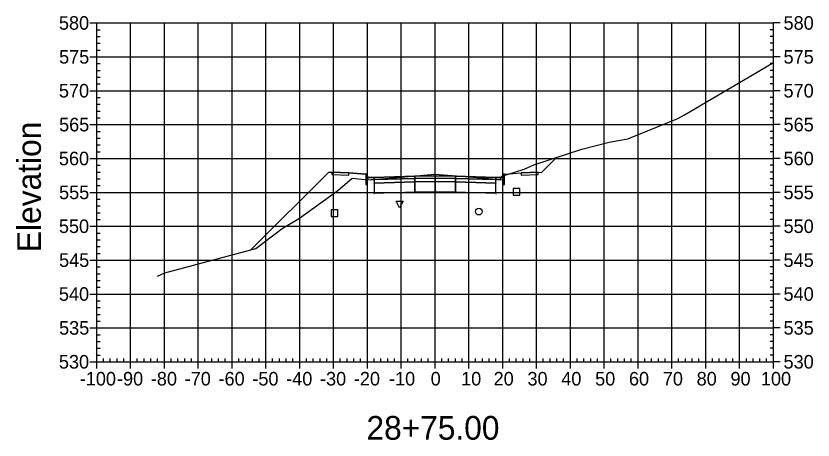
# Model space of a CAD drawing. Extents: x 704834 to 709892, y 372981 to 377533.
# Drawn here: x 708281 to 708516.6, y 377097.7 to 377222.9 of the extents above; entities that cross this region are included whole.
import ezdxf

# ---------------------------------------------------------------- set-up
doc = ezdxf.new("R2010")
doc.units = 0
for name, color, linetype in [('1', 7, 'Continuous'), ('10', 7, 'Continuous'), ('13', 7, 'Continuous'), ('14', 7, 'Continuous'), ('4', 7, 'Continuous'), ('57', 7, 'Continuous'), ('60', 7, 'Continuous'), ('Default_Xsect', 7, 'Continuous'), ('Existing', 7, 'Continuous')]:
    doc.layers.add(name, color=color, linetype=linetype)

msp = doc.modelspace()

# ---------------------------------------------------------------- linework, layer by layer
for points in [[(708436.41, 377176.72), (708440.81, 377181.12)], [(708373.41, 377176.72), (708350.61, 377153.92)], [(708374.41, 377176.76), (708373.41, 377176.72)], [(708435.41, 377176.76), (708436.41, 377176.72)], [(708384.41, 377176.16), (708379.41, 377176.56)], [(708425.41, 377176.16), (708430.41, 377176.56)]]:
    msp.add_lwpolyline(points)
for points in [[(708379.41, 377176.56), (708374.41, 377176.76), (708374.41, 377176.09), (708379.41, 377175.89)], [(708430.41, 377175.89), (708435.41, 377176.09), (708435.41, 377176.76), (708430.41, 377176.56)], [(708384.91, 377175.16), (708384.83, 377176.16), (708384.41, 377176.16), (708384.41, 377173.16), (708384.91, 377173.16)], [(708386.91, 377175.24), (708384.91, 377175.16), (708384.91, 377174.49), (708386.91, 377174.57)], [(708398.91, 377175.6), (708386.91, 377175.24), (708386.91, 377174.57), (708398.91, 377174.93)], [(708398.91, 377174.93), (708386.91, 377174.57), (708386.91, 377173.57), (708398.91, 377173.93)], [(708398.86, 377174.88), (708398.96, 377174.88), (708398.96, 377174.98), (708398.86, 377174.98)], [(708404.91, 377175.72), (708398.91, 377175.6), (708398.91, 377174.93), (708404.91, 377175.05)], [(708404.91, 377175.05), (708398.91, 377174.93), (708398.91, 377173.93), (708404.91, 377174.05)], [(708404.86, 377175), (708404.96, 377175), (708404.96, 377175.1), (708404.86, 377175.1)], [(708404.91, 377175.05), (708410.91, 377174.93), (708410.91, 377175.6), (708404.91, 377175.72)], [(708404.91, 377174.05), (708410.91, 377173.93), (708410.91, 377174.93), (708404.91, 377175.05)], [(708410.86, 377174.88), (708410.96, 377174.88), (708410.96, 377174.98), (708410.86, 377174.98)], [(708410.91, 377174.93), (708422.91, 377174.57), (708422.91, 377175.24), (708410.91, 377175.6)], [(708410.91, 377173.93), (708422.91, 377173.57), (708422.91, 377174.57), (708410.91, 377174.93)], [(708422.91, 377174.57), (708424.91, 377174.49), (708424.91, 377175.16), (708422.91, 377175.24)], [(708424.91, 377173.16), (708425.41, 377173.16), (708425.41, 377176.16), (708425, 377176.16), (708424.91, 377175.16)], [(708386.86, 377173.52), (708386.96, 377173.52), (708386.96, 377173.62), (708386.86, 377173.62)], [(708398.91, 377173.93), (708386.91, 377173.57), (708386.91, 377170.57), (708398.91, 377170.93)], [(708398.86, 377173.88), (708398.96, 377173.88), (708398.96, 377173.98), (708398.86, 377173.98)], [(708404.91, 377174.05), (708398.91, 377173.93), (708398.91, 377170.93), (708404.91, 377171.05)], [(708404.86, 377174), (708404.96, 377174), (708404.96, 377174.1), (708404.86, 377174.1)], [(708404.91, 377171.05), (708410.91, 377170.93), (708410.91, 377173.93), (708404.91, 377174.05)], [(708410.86, 377173.88), (708410.96, 377173.88), (708410.96, 377173.98), (708410.86, 377173.98)], [(708410.91, 377170.93), (708422.91, 377170.57), (708422.91, 377173.57), (708410.91, 377173.93)], [(708422.86, 377173.52), (708422.96, 377173.52), (708422.96, 377173.62), (708422.86, 377173.62)], [(708386.86, 377170.52), (708386.96, 377170.52), (708386.96, 377170.62), (708386.86, 377170.62)], [(708398.86, 377170.88), (708398.96, 377170.88), (708398.96, 377170.98), (708398.86, 377170.98)], [(708404.86, 377171), (708404.96, 377171), (708404.96, 377171.1), (708404.86, 377171.1)], [(708410.86, 377170.88), (708410.96, 377170.88), (708410.96, 377170.98), (708410.86, 377170.98)], [(708422.86, 377170.52), (708422.96, 377170.52), (708422.96, 377170.62), (708422.86, 377170.62)]]:
    msp.add_lwpolyline(points, close=True)
at = {"layer": '1'}
msp.add_lwpolyline([(708394.45, 377166.26), (708393.45, 377168.26), (708395.45, 377168.26)], close=True, dxfattribs=at)
at = {"layer": '10'}
msp.add_lwpolyline([(708374.17, 377163.68), (708376.17, 377163.68), (708376.17, 377165.68), (708374.17, 377165.68)], close=True, dxfattribs=at)
at = {"layer": '13'}
msp.add_circle((708417.85, 377165.14), 1, dxfattribs=at)
at = {"layer": '14'}
for points in [[(708440.81, 377181.12), (708440.81, 377181.17), (708440.81, 377181.12), (708440.76, 377181.12), (708440.81, 377181.12), (708440.81, 377181.07), (708440.81, 377181.12), (708440.86, 377181.12)], [(708386.91, 377175.24), (708386.91, 377175.29), (708386.91, 377175.24), (708386.86, 377175.24), (708386.91, 377175.24), (708386.91, 377175.19), (708386.91, 377175.24), (708386.96, 377175.24)], [(708404.91, 377175.72), (708404.91, 377175.77), (708404.91, 377175.72), (708404.86, 377175.72), (708404.91, 377175.72), (708404.91, 377175.67), (708404.91, 377175.72), (708404.96, 377175.72)], [(708422.91, 377175.24), (708422.91, 377175.29), (708422.91, 377175.24), (708422.86, 377175.24), (708422.91, 377175.24), (708422.91, 377175.19), (708422.91, 377175.24), (708422.96, 377175.24)], [(708350.61, 377153.92), (708350.61, 377153.97), (708350.61, 377153.92), (708350.56, 377153.92), (708350.61, 377153.92), (708350.61, 377153.87), (708350.61, 377153.92), (708350.66, 377153.92)]]:
    msp.add_lwpolyline(points, dxfattribs=at)
at = {"layer": '4'}
msp.add_lwpolyline([(708427.97, 377169.95), (708429.97, 377169.95), (708429.97, 377171.95), (708427.97, 377171.95)], close=True, dxfattribs=at)
at = {"layer": '57'}
for p, q in [((708302.91, 377220.82), (708304.91, 377220.82)), ((708304.91, 377220.82), (708504.91, 377220.82)), ((708304.91, 377120.82), (708304.91, 377220.82)), ((708304.91, 377120.82), (708304.91, 377220.82)), ((708314.91, 377120.82), (708314.91, 377220.82)), ((708324.91, 377120.82), (708324.91, 377220.82)), ((708334.91, 377120.82), (708334.91, 377220.82)), ((708344.91, 377120.82), (708344.91, 377220.82)), ((708354.91, 377120.82), (708354.91, 377220.82)), ((708364.91, 377120.82), (708364.91, 377220.82)), ((708374.91, 377120.82), (708374.91, 377220.82)), ((708384.91, 377120.82), (708384.91, 377220.82)), ((708394.91, 377120.82), (708394.91, 377220.82)), ((708404.91, 377120.82), (708404.91, 377220.82)), ((708414.91, 377120.82), (708414.91, 377220.82)), ((708424.91, 377120.82), (708424.91, 377220.82)), ((708434.91, 377120.82), (708434.91, 377220.82)), ((708444.91, 377120.82), (708444.91, 377220.82)), ((708454.91, 377120.82), (708454.91, 377220.82)), ((708464.91, 377120.82), (708464.91, 377220.82)), ((708474.91, 377120.82), (708474.91, 377220.82)), ((708484.91, 377120.82), (708484.91, 377220.82)), ((708494.91, 377120.82), (708494.91, 377220.82)), ((708504.91, 377120.82), (708504.91, 377220.82)), ((708504.91, 377120.82), (708504.91, 377220.82)), ((708506.91, 377220.82), (708504.91, 377220.82)), ((708304.91, 377218.82), (708305.91, 377218.82)), ((708304.91, 377216.82), (708305.91, 377216.82)), ((708504.91, 377218.82), (708503.91, 377218.82)), ((708504.91, 377216.82), (708503.91, 377216.82)), ((708304.91, 377214.82), (708305.91, 377214.82)), ((708504.91, 377214.82), (708503.91, 377214.82)), ((708304.91, 377212.82), (708305.91, 377212.82)), ((708504.91, 377212.82), (708503.91, 377212.82)), ((708302.91, 377210.82), (708304.91, 377210.82)), ((708304.91, 377210.82), (708504.91, 377210.82)), ((708506.91, 377210.82), (708504.91, 377210.82)), ((708304.91, 377208.82), (708305.91, 377208.82)), ((708504.91, 377208.82), (708503.91, 377208.82)), ((708304.91, 377206.82), (708305.91, 377206.82)), ((708504.91, 377206.82), (708503.91, 377206.82)), ((708304.91, 377204.82), (708305.91, 377204.82)), ((708304.91, 377202.82), (708305.91, 377202.82)), ((708504.91, 377204.82), (708503.91, 377204.82)), ((708504.91, 377202.82), (708503.91, 377202.82)), ((708302.91, 377200.82), (708304.91, 377200.82)), ((708304.91, 377200.82), (708504.91, 377200.82)), ((708506.91, 377200.82), (708504.91, 377200.82)), ((708304.91, 377198.82), (708305.91, 377198.82)), ((708504.91, 377198.82), (708503.91, 377198.82)), ((708304.91, 377196.82), (708305.91, 377196.82)), ((708504.91, 377196.82), (708503.91, 377196.82)), ((708304.91, 377194.82), (708305.91, 377194.82)), ((708504.91, 377194.82), (708503.91, 377194.82)), ((708302.91, 377190.82), (708304.91, 377190.82)), ((708304.91, 377192.82), (708305.91, 377192.82)), ((708304.91, 377190.82), (708504.91, 377190.82)), ((708504.91, 377192.82), (708503.91, 377192.82)), ((708506.91, 377190.82), (708504.91, 377190.82)), ((708304.91, 377188.82), (708305.91, 377188.82)), ((708504.91, 377188.82), (708503.91, 377188.82)), ((708304.91, 377186.82), (708305.91, 377186.82)), ((708504.91, 377186.82), (708503.91, 377186.82)), ((708304.91, 377184.82), (708305.91, 377184.82)), ((708504.91, 377184.82), (708503.91, 377184.82)), ((708304.91, 377182.82), (708305.91, 377182.82)), ((708504.91, 377182.82), (708503.91, 377182.82)), ((708302.91, 377180.82), (708304.91, 377180.82)), ((708304.91, 377180.82), (708504.91, 377180.82)), ((708506.91, 377180.82), (708504.91, 377180.82)), ((708304.91, 377178.82), (708305.91, 377178.82)), ((708304.91, 377176.82), (708305.91, 377176.82)), ((708504.91, 377178.82), (708503.91, 377178.82)), ((708504.91, 377176.82), (708503.91, 377176.82)), ((708304.91, 377174.82), (708305.91, 377174.82)), ((708504.91, 377174.82), (708503.91, 377174.82)), ((708304.91, 377172.82), (708305.91, 377172.82)), ((708504.91, 377172.82), (708503.91, 377172.82)), ((708302.91, 377170.82), (708304.91, 377170.82)), ((708304.91, 377170.82), (708504.91, 377170.82)), ((708506.91, 377170.82), (708504.91, 377170.82)), ((708304.91, 377168.82), (708305.91, 377168.82)), ((708504.91, 377168.82), (708503.91, 377168.82)), ((708304.91, 377166.82), (708305.91, 377166.82)), ((708304.91, 377164.82), (708305.91, 377164.82)), ((708504.91, 377166.82), (708503.91, 377166.82)), ((708504.91, 377164.82), (708503.91, 377164.82)), ((708304.91, 377162.82), (708305.91, 377162.82)), ((708504.91, 377162.82), (708503.91, 377162.82)), ((708302.91, 377160.82), (708304.91, 377160.82)), ((708304.91, 377160.82), (708504.91, 377160.82)), ((708506.91, 377160.82), (708504.91, 377160.82)), ((708304.91, 377158.82), (708305.91, 377158.82)), ((708504.91, 377158.82), (708503.91, 377158.82)), ((708304.91, 377156.82), (708305.91, 377156.82)), ((708504.91, 377156.82), (708503.91, 377156.82)), ((708304.91, 377154.82), (708305.91, 377154.82)), ((708504.91, 377154.82), (708503.91, 377154.82)), ((708302.91, 377150.82), (708304.91, 377150.82)), ((708304.91, 377152.82), (708305.91, 377152.82)), ((708304.91, 377150.82), (708504.91, 377150.82)), ((708504.91, 377152.82), (708503.91, 377152.82)), ((708506.91, 377150.82), (708504.91, 377150.82)), ((708304.91, 377148.82), (708305.91, 377148.82)), ((708504.91, 377148.82), (708503.91, 377148.82)), ((708304.91, 377146.82), (708305.91, 377146.82)), ((708504.91, 377146.82), (708503.91, 377146.82)), ((708304.91, 377144.82), (708305.91, 377144.82)), ((708504.91, 377144.82), (708503.91, 377144.82)), ((708304.91, 377142.82), (708305.91, 377142.82)), ((708504.91, 377142.82), (708503.91, 377142.82)), ((708302.91, 377140.82), (708304.91, 377140.82)), ((708304.91, 377140.82), (708504.91, 377140.82)), ((708506.91, 377140.82), (708504.91, 377140.82)), ((708304.91, 377138.82), (708305.91, 377138.82)), ((708304.91, 377136.82), (708305.91, 377136.82)), ((708504.91, 377138.82), (708503.91, 377138.82)), ((708504.91, 377136.82), (708503.91, 377136.82)), ((708304.91, 377134.82), (708305.91, 377134.82)), ((708504.91, 377134.82), (708503.91, 377134.82)), ((708304.91, 377132.82), (708305.91, 377132.82)), ((708504.91, 377132.82), (708503.91, 377132.82)), ((708302.91, 377130.82), (708304.91, 377130.82)), ((708304.91, 377130.82), (708504.91, 377130.82)), ((708506.91, 377130.82), (708504.91, 377130.82)), ((708304.91, 377128.82), (708305.91, 377128.82)), ((708504.91, 377128.82), (708503.91, 377128.82)), ((708304.91, 377126.82), (708305.91, 377126.82)), ((708304.91, 377124.82), (708305.91, 377124.82)), ((708504.91, 377126.82), (708503.91, 377126.82)), ((708504.91, 377124.82), (708503.91, 377124.82)), ((708304.91, 377122.82), (708305.91, 377122.82)), ((708504.91, 377122.82), (708503.91, 377122.82)), ((708302.91, 377120.82), (708304.91, 377120.82)), ((708304.91, 377120.82), (708504.91, 377120.82)), ((708304.91, 377120.82), (708504.91, 377120.82)), ((708304.91, 377118.82), (708304.91, 377120.82)), ((708306.91, 377120.82), (708306.91, 377121.82)), ((708308.91, 377120.82), (708308.91, 377121.82)), ((708310.91, 377120.82), (708310.91, 377121.82)), ((708312.91, 377120.82), (708312.91, 377121.82)), ((708314.91, 377118.82), (708314.91, 377120.82)), ((708316.91, 377120.82), (708316.91, 377121.82)), ((708318.91, 377120.82), (708318.91, 377121.82)), ((708320.91, 377120.82), (708320.91, 377121.82)), ((708322.91, 377120.82), (708322.91, 377121.82)), ((708324.91, 377118.82), (708324.91, 377120.82)), ((708326.91, 377120.82), (708326.91, 377121.82)), ((708328.91, 377120.82), (708328.91, 377121.82)), ((708330.91, 377120.82), (708330.91, 377121.82)), ((708332.91, 377120.82), (708332.91, 377121.82)), ((708334.91, 377118.82), (708334.91, 377120.82)), ((708336.91, 377120.82), (708336.91, 377121.82)), ((708338.91, 377120.82), (708338.91, 377121.82)), ((708340.91, 377120.82), (708340.91, 377121.82)), ((708342.91, 377120.82), (708342.91, 377121.82)), ((708344.91, 377118.82), (708344.91, 377120.82)), ((708346.91, 377120.82), (708346.91, 377121.82)), ((708348.91, 377120.82), (708348.91, 377121.82)), ((708350.91, 377120.82), (708350.91, 377121.82)), ((708352.91, 377120.82), (708352.91, 377121.82)), ((708354.91, 377118.82), (708354.91, 377120.82)), ((708356.91, 377120.82), (708356.91, 377121.82)), ((708358.91, 377120.82), (708358.91, 377121.82)), ((708360.91, 377120.82), (708360.91, 377121.82)), ((708362.91, 377120.82), (708362.91, 377121.82)), ((708364.91, 377118.82), (708364.91, 377120.82)), ((708366.91, 377120.82), (708366.91, 377121.82)), ((708368.91, 377120.82), (708368.91, 377121.82)), ((708370.91, 377120.82), (708370.91, 377121.82)), ((708372.91, 377120.82), (708372.91, 377121.82)), ((708374.91, 377118.82), (708374.91, 377120.82)), ((708376.91, 377120.82), (708376.91, 377121.82)), ((708378.91, 377120.82), (708378.91, 377121.82)), ((708380.91, 377120.82), (708380.91, 377121.82)), ((708382.91, 377120.82), (708382.91, 377121.82)), ((708384.91, 377118.82), (708384.91, 377120.82)), ((708386.91, 377120.82), (708386.91, 377121.82)), ((708388.91, 377120.82), (708388.91, 377121.82)), ((708390.91, 377120.82), (708390.91, 377121.82)), ((708392.91, 377120.82), (708392.91, 377121.82)), ((708394.91, 377118.82), (708394.91, 377120.82)), ((708396.91, 377120.82), (708396.91, 377121.82)), ((708398.91, 377120.82), (708398.91, 377121.82)), ((708400.91, 377120.82), (708400.91, 377121.82)), ((708402.91, 377120.82), (708402.91, 377121.82)), ((708404.91, 377118.82), (708404.91, 377120.82)), ((708406.91, 377120.82), (708406.91, 377121.82)), ((708408.91, 377120.82), (708408.91, 377121.82)), ((708410.91, 377120.82), (708410.91, 377121.82)), ((708412.91, 377120.82), (708412.91, 377121.82)), ((708414.91, 377118.82), (708414.91, 377120.82)), ((708416.91, 377120.82), (708416.91, 377121.82)), ((708418.91, 377120.82), (708418.91, 377121.82)), ((708420.91, 377120.82), (708420.91, 377121.82)), ((708422.91, 377120.82), (708422.91, 377121.82)), ((708424.91, 377118.82), (708424.91, 377120.82)), ((708426.91, 377120.82), (708426.91, 377121.82)), ((708428.91, 377120.82), (708428.91, 377121.82)), ((708430.91, 377120.82), (708430.91, 377121.82)), ((708432.91, 377120.82), (708432.91, 377121.82)), ((708434.91, 377118.82), (708434.91, 377120.82)), ((708436.91, 377120.82), (708436.91, 377121.82)), ((708438.91, 377120.82), (708438.91, 377121.82)), ((708440.91, 377120.82), (708440.91, 377121.82)), ((708442.91, 377120.82), (708442.91, 377121.82)), ((708444.91, 377118.82), (708444.91, 377120.82)), ((708446.91, 377120.82), (708446.91, 377121.82)), ((708448.91, 377120.82), (708448.91, 377121.82)), ((708450.91, 377120.82), (708450.91, 377121.82)), ((708452.91, 377120.82), (708452.91, 377121.82)), ((708454.91, 377118.82), (708454.91, 377120.82)), ((708456.91, 377120.82), (708456.91, 377121.82)), ((708458.91, 377120.82), (708458.91, 377121.82)), ((708460.91, 377120.82), (708460.91, 377121.82)), ((708462.91, 377120.82), (708462.91, 377121.82)), ((708464.91, 377118.82), (708464.91, 377120.82)), ((708466.91, 377120.82), (708466.91, 377121.82)), ((708468.91, 377120.82), (708468.91, 377121.82)), ((708470.91, 377120.82), (708470.91, 377121.82)), ((708472.91, 377120.82), (708472.91, 377121.82)), ((708474.91, 377118.82), (708474.91, 377120.82)), ((708476.91, 377120.82), (708476.91, 377121.82)), ((708478.91, 377120.82), (708478.91, 377121.82)), ((708480.91, 377120.82), (708480.91, 377121.82)), ((708482.91, 377120.82), (708482.91, 377121.82)), ((708484.91, 377118.82), (708484.91, 377120.82)), ((708486.91, 377120.82), (708486.91, 377121.82)), ((708488.91, 377120.82), (708488.91, 377121.82)), ((708490.91, 377120.82), (708490.91, 377121.82)), ((708492.91, 377120.82), (708492.91, 377121.82)), ((708494.91, 377118.82), (708494.91, 377120.82)), ((708496.91, 377120.82), (708496.91, 377121.82)), ((708498.91, 377120.82), (708498.91, 377121.82)), ((708500.91, 377120.82), (708500.91, 377121.82)), ((708502.91, 377120.82), (708502.91, 377121.82)), ((708504.91, 377118.82), (708504.91, 377120.82)), ((708506.91, 377120.82), (708504.91, 377120.82))]:
    msp.add_line(p, q, dxfattribs=at)
at = {"layer": 'Default_Xsect'}
msp.add_lwpolyline([(708350.61, 377153.92), (708373.41, 377176.72), (708374.41, 377176.76), (708379.41, 377176.56), (708384.41, 377176.16), (708384.83, 377176.16), (708384.91, 377175.16), (708386.91, 377175.24), (708398.91, 377175.6), (708404.91, 377175.72), (708410.91, 377175.6), (708422.91, 377175.24), (708424.91, 377175.16), (708425, 377176.16), (708425.41, 377176.16), (708430.41, 377176.56), (708435.41, 377176.76), (708436.41, 377176.72), (708440.81, 377181.12)], dxfattribs=at)
at = {"layer": 'Existing'}
msp.add_lwpolyline([(708322.84, 377146.05), (708325.08, 377147.08), (708351.95, 377154.27), (708359.77, 377160.16), (708364.83, 377163.17), (708376.17, 377171.4), (708380.45, 377174.98), (708384.08, 377174.65), (708385.88, 377174.51), (708386.15, 377174.58), (708386.56, 377174.66), (708392.52, 377175.09), (708404.8, 377176.15), (708415.09, 377175.37), (708424.2, 377174.6), (708424.45, 377175.16), (708424.64, 377175.58), (708428.5, 377176.81), (708431.22, 377177.62), (708434.08, 377178.9), (708448.25, 377183.56), (708456.36, 377185.6), (708461.88, 377186.66), (708476.68, 377192.65), (708478.63, 377193.67), (708499.46, 377205.9), (708504.91, 377209.14)], dxfattribs=at)

# ---------------------------------------------------------------- texts
at = {"layer": '1'}
msp.add_text('28+75.00', height=7, dxfattribs=at).set_placement((708384.64, 377097.82))
at = {"layer": '14'}
for p in [(708374.38, 377176.71), (708435.38, 377176.71), (708374.38, 377176.04), (708379.38, 377175.84), (708430.38, 377175.84), (708435.38, 377176.04)]:
    msp.add_text('+', height=0.1, dxfattribs=at).set_placement(p)
at = {"layer": '57'}
for s, p in [('580', (708293.74, 377218.82)), ('580', (708507.91, 377218.82)), ('575', (708293.79, 377208.82)), ('575', (708507.91, 377208.82)), ('570', (708293.74, 377198.82)), ('570', (708507.91, 377198.82)), ('565', (708293.79, 377188.82)), ('565', (708507.91, 377188.82)), ('560', (708293.74, 377178.82)), ('560', (708507.91, 377178.82)), ('555', (708293.79, 377168.82)), ('555', (708507.91, 377168.82)), ('550', (708293.74, 377158.82)), ('550', (708507.91, 377158.82)), ('545', (708293.79, 377148.82)), ('545', (708507.91, 377148.82)), ('540', (708293.74, 377138.82)), ('540', (708507.91, 377138.82)), ('535', (708293.79, 377128.82)), ('535', (708507.91, 377128.82)), ('530', (708293.74, 377118.82)), ('530', (708507.91, 377118.82)), ('-100', (708299.9, 377113.82)), ('-90', (708310.91, 377113.82)), ('-80', (708320.91, 377113.82)), ('-70', (708330.91, 377113.82)), ('-60', (708340.91, 377113.82)), ('-50', (708350.91, 377113.82)), ('-40', (708360.91, 377113.82)), ('-30', (708370.91, 377113.82)), ('-20', (708380.91, 377113.82)), ('-10', (708391.3, 377113.82)), ('0', (708403.62, 377113.82)), ('10', (708412.61, 377113.82)), ('20', (708422.22, 377113.82)), ('30', (708432.22, 377113.82)), ('40', (708442.22, 377113.82)), ('50', (708452.22, 377113.82)), ('60', (708462.22, 377113.82)), ('70', (708472.22, 377113.82)), ('80', (708482.22, 377113.82)), ('90', (708492.22, 377113.82)), ('100', (708501.21, 377113.82))]:
    msp.add_text(s, height=4, dxfattribs=at).set_placement(p)
at = {"layer": '60'}
msp.add_text('Elevation', height=7, rotation=90, dxfattribs=at).set_placement((708288.41, 377153.18))

doc.saveas('drawing.dxf')
